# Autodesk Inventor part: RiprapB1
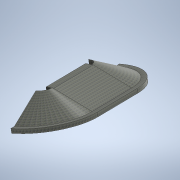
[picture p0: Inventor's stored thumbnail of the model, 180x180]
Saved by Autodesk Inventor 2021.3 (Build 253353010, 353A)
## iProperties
Created: 2021-11
Part Number: RiprapB1
Material: Generic
Document SubType Name: Modeling
Designer: u1426
Density: 1 g/cm^3
Appearance: Rubble - River Rock
Author: u1426
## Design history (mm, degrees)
sketch "Sketch1"
  geometry: L1 (1207.008, -914.4)-(1394.474, -2788.948); L2 (1394.474, -2788.948)-(5858.256, -11716.512); L3 (5858.256, -13024.651)-(6925.056, -13024.651); L4 (6925.056, -13024.651)-(6925.056, -11805.451); L5 (6925.056, -11805.451)-(2287.591, -2530.521); L6 (2287.591, -2530.521)-(2125.969, -914.4); L7 (2125.969, -914.4)-(1207.008, -914.4); L8 (1394.474, -2788.948)-(0, 0); L9 (1207.008, 0)-(0, 0); L10 (5858.256, -13024.651)-(5858.256, -11716.512); L11 (1207.008, 0)-(1207.008, -914.4)
  constraints: 22 end point, 2 horizontal, 2 parallel, 2 perpendicular, 2 vertical, 1 collinear, 1 other
  dimensions: "d0" = 1066.8 distance of L3.start L3.end; "d1" = 1219.2 distance of L3.end L4.end; "d2" = 914.4 distance between parallel lines of L5 L2; "d3" = 914.4 distance between parallel lines of L6 L1; "d20" = 84.2891 deg angle of L1 L7; "d23" = 1207.008 distance of L9.start L8.end; "d24" = 63.4349 deg angle of L8 L9; "d25" = 5858.256 distance from line of L8.end L10 (= SpillPtElev - ToeElev); "d26" = 1874.54794 vertical distance of L1.start L1.end (derived); "d27" = 11716.512 distance from line of L9 L2.end (derived); "d28" = 914.4 distance between parallel lines of L9 L7
extrude "Extrusion1" new body sketch "Sketch1" stored distance "d8" = 14935.2; taper "d9" = 0 deg
sketch "Sketch2"
  geometry: L1 (0, 0)-(-4569.376, 0); L2 (-5858.256, -11716.512)-(-1394.474, -2788.948) reference; L3 (-2287.591, -2530.521)-(-6925.056, -11805.451) reference; L4 (-6925.056, -11805.451)-(-6925.056, -13024.651) reference; L5 (-6925.056, -13024.651)-(-5858.256, -13024.651) reference; L6 (-5858.256, -13024.651)-(-5858.256, -11716.512) reference; L7 (-1394.474, -2788.948)-(-5858.256, -11716.512) reference; L8 (-1394.474, -2788.948)-(-1252.728, -2505.456); L9 (-1252.728, -2505.456)-(-2275.058, -2505.456); L10 (-2287.591, -2530.521)-(-2125.969, -914.4) reference; L11 (-2275.058, -2505.456)-(-2287.591, -2530.521)
  constraints: 8 end point, 2 collinear, 2 horizontal
  dimensions: "d29" = 4605.528 distance from line of L8.end L6 (= TopRRElev - ToeElev)
revolve "Revolution1" sketch "Sketch2" stored, may be unused: angle "d30" = 90 deg
sketch "Sketch3"
  geometry: L1 (-1394.474, 2788.948)-(-5858.256, 11716.512) reference; L2 (-6925.056, 11805.451)-(-2287.591, 2530.521) reference; L3 (-6925.056, 13024.651)-(-6925.056, 11805.451) reference; L4 (-5858.256, 13024.651)-(-6925.056, 13024.651) reference; L5 (-5858.256, 11716.512)-(-5858.256, 13024.651) reference; L6 (-1394.474, 2788.948)-(-1252.728, 2505.456) reference; L7 (-1252.728, 2505.456)-(-1366.123, 2505.456) reference; L8 (-2287.591, 2530.521)-(-2275.058, 2505.456) reference; L9 (0, 0)-(-4606.323, 0); L10 (-5858.256, 0)-(-1252.728, 0) reference; L11 (-2275.058, 2505.456)-(-1366.123, 2505.456) reference
  constraints: 2 end point, 1 point on line
revolve "Revolution2" sketch "Sketch3" stored, may be unused: angle "d31" = 90 deg
body "Solid1"
other parameters: "TopRRCapElev" = 865464.36 [user parameter], "ToeElev" = 860813.112 [user parameter; used in 2 equation terms], "TopRRElev" = 865418.64 [user parameter; used in 1 equation term], "SpillPtElev" = 866671.368 [user parameter; used in 1 equation term]
